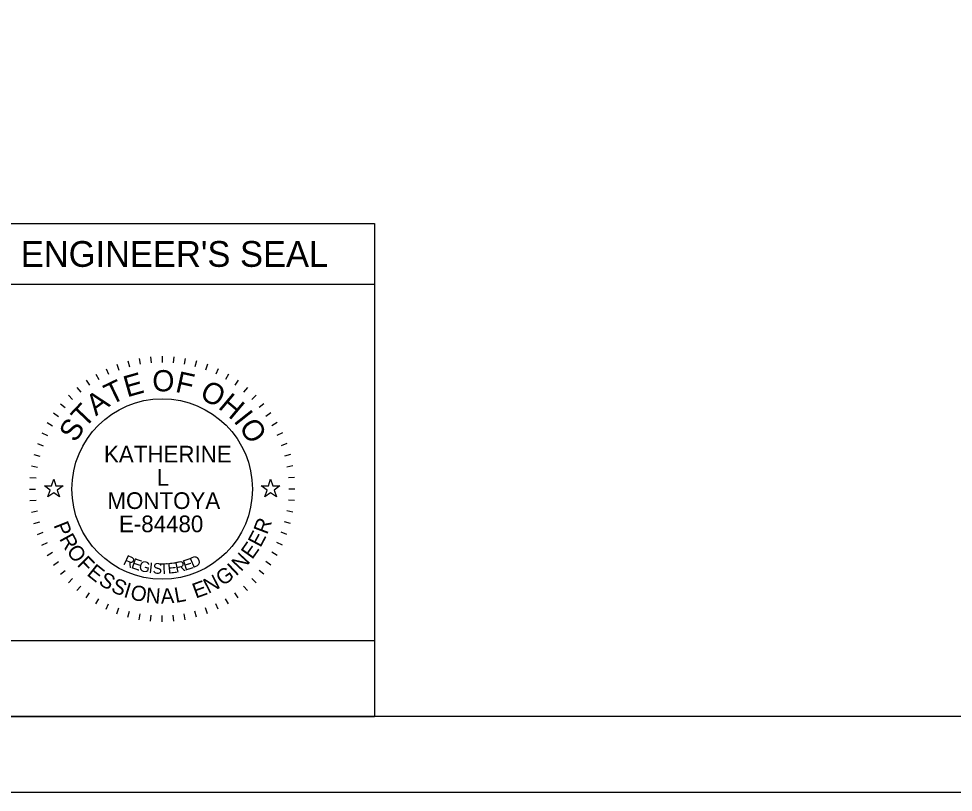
# Model space of a CAD drawing. Extents: x 0 to 34, y 0 to 22.
# Drawn here: x 23.62 to 29.78, y 0 to 5.1 of the extents above; entities that cross this region are included whole.
import ezdxf

# ---------------------------------------------------------------- set-up
doc = ezdxf.new("R2010")
doc.units = 0
for name, color, linetype in [('SH_Border', 7, 'Continuous'), ('SH_Cut_Line', 7, 'Continuous'), ('SH_Data', 7, 'Continuous'), ('SH_Seal', 7, 'Continuous')]:
    doc.layers.add(name, color=color, linetype=linetype)

msp = doc.modelspace()

# ---------------------------------------------------------------- linework, layer by layer
at = {"layer": 'SH_Border'}
msp.add_lwpolyline([(1.5, 21.5), (33.5, 21.5), (33.5, 0.5), (1.5, 0.5)], close=True, dxfattribs=at)
at = {"layer": 'SH_Cut_Line'}
msp.add_lwpolyline([(0, 0), (34, 0), (34, 22), (0, 22)], close=True, dxfattribs=at)
at = {"layer": 'SH_Data'}
for p, q in [((23.1618, 3.75), (25.9618, 3.75)), ((25.9618, 3.75), (25.9618, 0.5)), ((23.1618, 3.35), (25.9618, 3.35)), ((23.1618, 0.5), (25.9618, 0.5))]:
    msp.add_line(p, q, dxfattribs=at)
msp.add_lwpolyline([(23.1618, 0.5), (23.1618, 1), (25.9618, 1), (25.9618, 0.5)], close=True, dxfattribs=at)
at = {"layer": 'SH_Seal'}
for p, q in [((24.3353, 2.8452), (24.3457, 2.8065)), ((24.4098, 2.8617), (24.4168, 2.8223)), ((24.4855, 2.8717), (24.489, 2.8318)), ((24.5618, 2.875), (24.5618, 2.835)), ((24.638, 2.8717), (24.6345, 2.8318)), ((24.7137, 2.8617), (24.7068, 2.8223)), ((24.7882, 2.8452), (24.7779, 2.8065)), ((24.192, 2.793), (24.2089, 2.7568)), ((24.2625, 2.8222), (24.2762, 2.7846)), ((24.861, 2.8222), (24.8474, 2.7846)), ((24.9316, 2.793), (24.9147, 2.7568)), ((24.0599, 2.7168), (24.0828, 2.684)), ((24.1243, 2.7578), (24.1443, 2.7231)), ((24.9993, 2.7578), (24.9793, 2.7231)), ((25.0637, 2.7168), (25.0407, 2.684)), ((23.9993, 2.6703), (24.025, 2.6396)), ((25.1242, 2.6703), (25.0985, 2.6396)), ((23.9431, 2.6187), (23.9713, 2.5904)), ((25.1805, 2.6187), (25.1522, 2.5904)), ((23.8915, 2.5624), (23.9221, 2.5367)), ((25.2321, 2.5624), (25.2014, 2.5367)), ((23.845, 2.5019), (23.8778, 2.4789)), ((25.2785, 2.5019), (25.2458, 2.4789)), ((23.804, 2.4375), (23.8386, 2.4175)), ((25.3195, 2.4375), (25.2849, 2.4175)), ((23.7688, 2.3698), (23.805, 2.3529)), ((25.3548, 2.3698), (25.3185, 2.3529)), ((23.7395, 2.2993), (23.7771, 2.2856)), ((25.384, 2.2993), (25.3464, 2.2856)), ((23.7166, 2.2265), (23.7552, 2.2161)), ((25.407, 2.2265), (25.3683, 2.2161)), ((23.7001, 2.1519), (23.7395, 2.145)), ((25.4235, 2.1519), (25.3841, 2.145)), ((23.6901, 2.0763), (23.73, 2.0728)), ((25.4334, 2.0763), (25.3936, 2.0728)), ((23.6868, 2), (23.7268, 2)), ((25.4368, 2), (25.3968, 2)), ((23.6901, 1.9237), (23.73, 1.9272)), ((25.4334, 1.9237), (25.3936, 1.9272)), ((23.7001, 1.8481), (23.7395, 1.855)), ((25.4235, 1.8481), (25.3841, 1.855)), ((23.7166, 1.7735), (23.7552, 1.7839)), ((25.407, 1.7735), (25.3683, 1.7839)), ((23.7395, 1.7007), (23.7771, 1.7144)), ((25.384, 1.7007), (25.3464, 1.7144)), ((23.7688, 1.6302), (23.805, 1.6471)), ((25.3548, 1.6302), (25.3185, 1.6471)), ((23.804, 1.5625), (23.8386, 1.5825)), ((25.3195, 1.5625), (25.2849, 1.5825)), ((23.845, 1.4981), (23.8778, 1.5211)), ((25.2785, 1.4981), (25.2458, 1.5211)), ((23.8915, 1.4376), (23.9221, 1.4633)), ((25.2321, 1.4376), (25.2014, 1.4633)), ((23.9431, 1.3813), (23.9713, 1.4096)), ((23.9993, 1.3297), (24.025, 1.3604)), ((25.1242, 1.3297), (25.0985, 1.3604)), ((25.1805, 1.3813), (25.1522, 1.4096)), ((24.0599, 1.2832), (24.0828, 1.316)), ((25.0637, 1.2832), (25.0407, 1.316)), ((24.1243, 1.2422), (24.1443, 1.2769)), ((24.192, 1.207), (24.2089, 1.2432)), ((24.9316, 1.207), (24.9147, 1.2432)), ((24.9993, 1.2422), (24.9793, 1.2769)), ((24.2625, 1.1778), (24.2762, 1.2154)), ((24.3353, 1.1548), (24.3457, 1.1935)), ((24.4098, 1.1383), (24.4168, 1.1777)), ((24.7137, 1.1383), (24.7068, 1.1777)), ((24.7882, 1.1548), (24.7779, 1.1935)), ((24.861, 1.1778), (24.8474, 1.2154)), ((24.4855, 1.1283), (24.489, 1.1682)), ((24.5618, 1.125), (24.5618, 1.165)), ((24.638, 1.1283), (24.6345, 1.1682))]:
    msp.add_line(p, q, dxfattribs=at)
for points in [[(23.7854, 2.02), (23.8323, 2.02), (23.8468, 2.0645), (23.8613, 2.02), (23.9082, 2.02), (23.8703, 1.9924), (23.8848, 1.9478), (23.8468, 1.9754), (23.8088, 1.9478), (23.8233, 1.9924)], [(25.2154, 2.02), (25.2623, 2.02), (25.2768, 2.0645), (25.2913, 2.02), (25.3382, 2.02), (25.3003, 1.9924), (25.3148, 1.9478), (25.2768, 1.9754), (25.2388, 1.9478), (25.2533, 1.9924)]]:
    msp.add_lwpolyline(points, close=True, dxfattribs=at)
msp.add_circle((24.5618, 2), 0.595, dxfattribs=at)

# ---------------------------------------------------------------- texts
at = {"layer": 'SH_Data'}
msp.add_text("ENGINEER'S SEAL", height=0.17, dxfattribs=at).set_placement((23.6293, 3.465))
at = {"layer": 'SH_Seal'}
for s, height, rotation, p in [('O', 0.14, 359.78119, (24.4965, 2.6443)), ('F', 0.14, 347.43619, (24.6428, 2.6417)), ('T', 0.14, 25.71674, (24.2234, 2.5518)), ('E', 0.14, 15.75706, (24.3302, 2.6038)), ('O', 0.14, 332.25863, (24.8016, 2.6015)), ('A', 0.14, 36.47472, (24.1252, 2.4781)), ('H', 0.14, 319.91363, (24.9249, 2.5361)), ('T', 0.14, 46.4344, (24.0501, 2.3964)), ('I', 0.14, 308.36695, (25.0282, 2.4483)), ('S', 0.14, 57.19238, (23.9899, 2.3014)), ('O', 0.14, 303.14906, (25.0639, 2.4089)), ('P', 0.1, 291.49398, (23.844, 1.7621)), ('R', 0.1, 69.23216, (25.2537, 1.6954)), ('E', 0.1, 61.99508, (25.2094, 1.6098)), ('R', 0.1, 298.73106, (23.8807, 1.6717)), ('O', 0.1, 306.46664, (23.9272, 1.5883)), ('E', 0.1, 54.75801, (25.1551, 1.5314)), ('F', 0.1, 314.7068, (23.9961, 1.4983)), ('R', 0.07, 334.48695, (24.2993, 1.5051)), ('E', 0.07, 341.03996, (24.3524, 1.4801)), ('E', 0.07, 17.68363, (24.7116, 1.4602)), ('D', 0.07, 23.30524, (24.7628, 1.477)), ('N', 0.1, 47.02243, (25.082, 1.4508)), ('E', 0.1, 321.43929, (24.0596, 1.4348)), ('G', 0.07, 347.47515, (24.4032, 1.4618)), ('I', 0.07, 353.78581, (24.4708, 1.4468)), ('S', 0.07, 356.89262, (24.4975, 1.4429)), ('T', 0.07, 3.00609, (24.5475, 1.4387)), ('E', 0.07, 6.01169, (24.6007, 1.4412)), ('R', 0.07, 11.91844, (24.6543, 1.4474)), ('G', 0.1, 35.04687, (24.9598, 1.357)), ('I', 0.1, 43.28703, (25.0486, 1.4214)), ('S', 0.1, 328.67637, (24.1361, 1.3752)), ('N', 0.1, 27.31129, (24.8662, 1.3075)), ('S', 0.1, 335.91345, (24.2182, 1.3266)), ('I', 0.1, 343.15053, (24.3024, 1.2897)), ('O', 0.1, 346.88592, (24.3456, 1.2751)), ('E', 0.1, 20.07421, (24.783, 1.277)), ('N', 0.1, 355.12608, (24.4506, 1.2517)), ('A', 0.1, 2.86166, (24.5541, 1.2437)), ('L', 0.1, 10.09874, (24.6512, 1.249))]:
    msp.add_text(s, height=height, rotation=rotation, dxfattribs=at).set_placement(p)
for s, p in [('KATHERINE', (24.1781, 2.1749)), ('L', (24.5263, 2.0216)), ('MONTOYA', (24.2008, 1.8684)), ('E-84480', (24.2767, 1.7151))]:
    msp.add_text(s, height=0.11, dxfattribs=at).set_placement(p)

doc.saveas('drawing.dxf')
